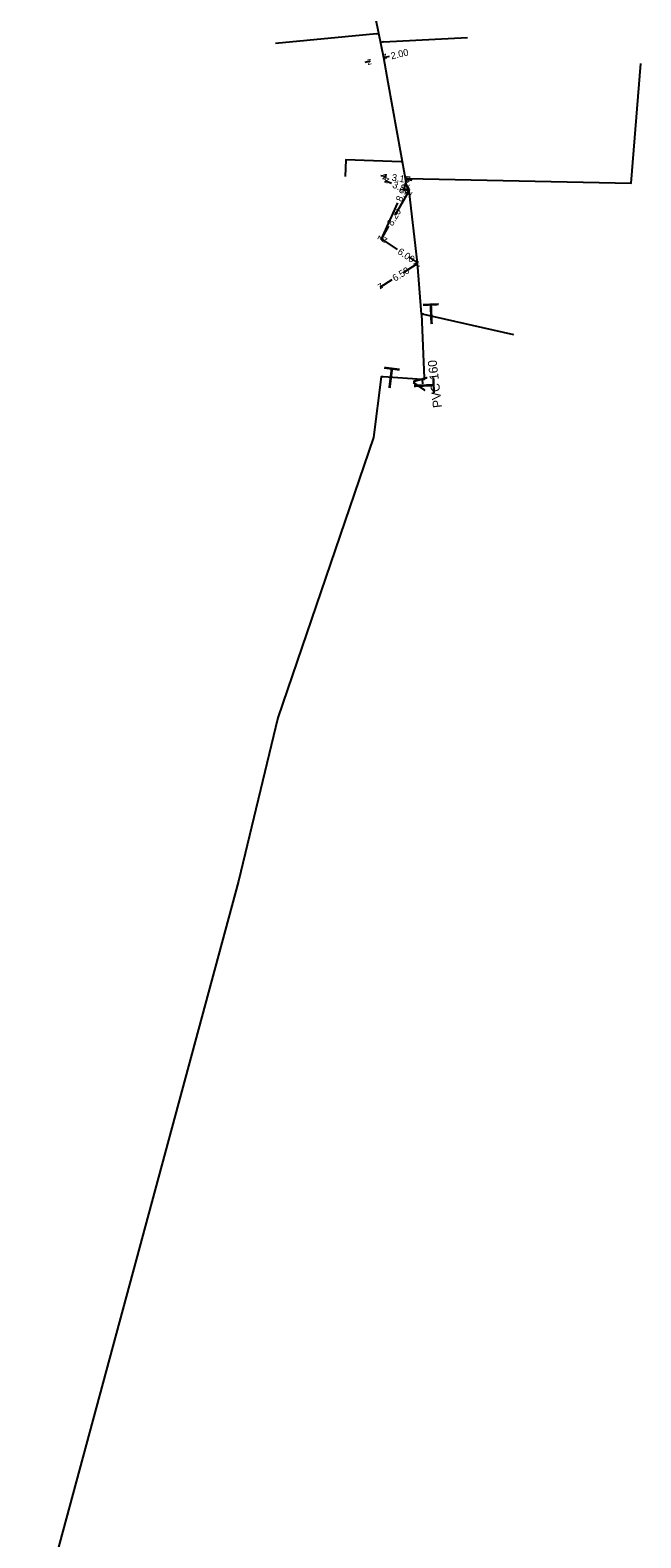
# Model space of a CAD drawing. Extents: x -634006 to -632185, y -1101085 to -1098649.
# Drawn here: x -633391.3 to -633302.8, y -1099867.2 to -1099648.6 of the extents above; entities that cross this region are included whole.
import ezdxf

# ---------------------------------------------------------------- set-up
doc = ezdxf.new("R2010")
doc.units = 0
for name, color, linetype in [('VP Hydrant', 7, 'Continuous'), ('VP Kótování', 7, 'Continuous'), ('VP Přípojka', 7, 'Continuous'), ('VP Řad', 7, 'Continuous'), ('VP Řad - popis', 7, 'Continuous'), ('VP Šoupě', 7, 'Continuous')]:
    doc.layers.add(name, color=color, linetype=linetype)

msp = doc.modelspace()

# ---------------------------------------------------------------- linework, layer by layer
at = {"layer": 'VP Kótování'}
for points in [[(-633342.75, -1099653.19), (-633342.02, -1099653.02)], [(-633339.3, -1099652.38), (-633340.08, -1099652.56)], [(-633340.51, -1099669.63), (-633339.77, -1099669.75)], [(-633338.96, -1099670.78), (-633339.87, -1099670.39)], [(-633339.82, -1099670.09), (-633339.72, -1099669.45)], [(-633339.62, -1099670.39), (-633339.62, -1099670.39)], [(-633337.19, -1099671.72), (-633336.81, -1099670.87)], [(-633337.15, -1099671.55), (-633336.38, -1099671.88)], [(-633337.11, -1099670.87), (-633337.11, -1099670.87)], [(-633336.76, -1099670.58), (-633336.66, -1099669.93)], [(-633335.97, -1099670.35), (-633336.71, -1099670.23)], [(-633338.06, -1099673.61), (-633340.51, -1099678.97)], [(-633338.38, -1099675.31), (-633336.38, -1099671.88)], [(-633336.62, -1099671.88), (-633336.63, -1099671.88)], [(-633336.59, -1099671.76), (-633336.59, -1099671.76)], [(-633339.37, -1099677.01), (-633340.51, -1099678.97)], [(-633340.72, -1099678.84), (-633340.72, -1099678.84)], [(-633340.3, -1099679.2), (-633340.3, -1099679.2)], [(-633340.21, -1099678.97), (-633340.21, -1099678.97)], [(-633338.1, -1099680.36), (-633340.16, -1099678.99)], [(-633337.23, -1099683.71), (-633335.16, -1099682.4)], [(-633336.41, -1099681.49), (-633335.16, -1099682.32)], [(-633334.92, -1099682.4), (-633334.92, -1099682.4)], [(-633335.3, -1099682.53), (-633335.3, -1099682.53)], [(-633338.92, -1099684.77), (-633340.66, -1099685.87)], [(-633340.41, -1099685.87), (-633340.41, -1099685.87)]]:
    msp.add_lwpolyline(points, dxfattribs=at)
at = {"layer": 'VP Přípojka'}
for points in [[(-633341.13, -1099649.11), (-633355.76, -1099650.52)], [(-633341.13, -1099649.11), (-633340.78, -1099649.04)], [(-633340.13, -1099650.26), (-633327.91, -1099649.64)], [(-633340.13, -1099650.26), (-633340.52, -1099650.34)], [(-633336.69, -1099670.06), (-633304.19, -1099670.74), (-633302.8, -1099653.42)], [(-633337.53, -1099667.65), (-633345.57, -1099667.37), (-633345.69, -1099669.79)], [(-633337.53, -1099667.65), (-633337.39, -1099667.62)], [(-633336.69, -1099670.06), (-633336.94, -1099670.09)], [(-633334.33, -1099689.74), (-633334.58, -1099689.75)], [(-633334.33, -1099689.74), (-633321.25, -1099692.67)], [(-633334.49, -1099699.2), (-633334.47, -1099699.86)]]:
    msp.add_lwpolyline(points, dxfattribs=at)
at = {"layer": 'VP Řad'}
for points in [[(-633334.58, -1099689.74), (-633335.16, -1099682.32), (-633336.38, -1099671.88), (-633336.81, -1099670.87), (-633336.94, -1099670.09), (-633339.43, -1099656.17), (-633340.08, -1099652.56), (-633340.82, -1099648.82), (-633344.28, -1099632.01)], [(-633334.58, -1099689.74), (-633334.23, -1099698.96), (-633334.22, -1099699.22), (-633334.49, -1099699.2), (-633340.18, -1099698.83), (-633340.43, -1099698.82), (-633341.54, -1099707.61), (-633355.45, -1099748.28), (-633361.15, -1099771.98), (-633389, -1099875.13), (-633391.35, -1099914.67), (-633358.54, -1100018.91), (-633322.36, -1100115.57), (-633326.19, -1100117.61)]]:
    msp.add_lwpolyline(points, dxfattribs=at)

# ---------------------------------------------------------------- texts
at = {"layer": 'VP Hydrant'}
msp.add_text('>', height=3, rotation=170.5409, dxfattribs=at).set_placement((-633333.48, -1099698.5))
at = {"layer": 'VP Kótování'}
for s, rotation, p in [('2.00', 13.326, (-633338.94, -1099652.81)), ('z', 13.326, (-633342.39, -1099653.62)), ('z', 193.326, (-633339.71, -1099651.96)), ('z', 351.0572, (-633340.34, -1099670.17)), ('z', 156.8622, (-633339.21, -1099670.13)), ('3.10', 351.0571, (-633338.97, -1099670.38)), ('3.80', 336.8622, (-633338.92, -1099671.34)), ('8.90', 65.4362, (-633337.48, -1099673.54)), ('z', 65.4362, (-633336.56, -1099671.53)), ('z', 336.8621, (-633337.03, -1099672.15)), ('z', 171.0572, (-633336.13, -1099669.81)), ('z', 59.7448, (-633336.2, -1099672.57)), ('8.20', 59.7448, (-633338.81, -1099677.05)), ('z', 245.4362, (-633340.75, -1099678.3)), ('z', 239.7448, (-633340.69, -1099678.28)), ('z', 146.3504, (-633339.46, -1099678.85)), ('6.00', 326.3505, (-633338.17, -1099680.91)), ('z', 326.3504, (-633335.86, -1099682.46)), ('z', 32.3011, (-633335.32, -1099683.09)), ('6.50', 32.3011, (-633338.44, -1099685.06)), ('z', 212.3011, (-633340.5, -1099685.18))]:
    msp.add_text(s, height=1, rotation=rotation, dxfattribs=at).set_placement(p)
at = {"layer": 'VP Řad - popis'}
msp.add_text('PVC 160', height=1.3, rotation=96.5547, dxfattribs=at).set_placement((-633331.63, -1099703.25))
at = {"layer": 'VP Šoupě'}
for rotation, p in [(2.3302, (-633334.36, -1099691.24)), (352.8365, (-633340.46, -1099700.31)), (272.3302, (-633335.73, -1099698.93))]:
    msp.add_text('T', height=3, rotation=rotation, dxfattribs=at).set_placement(p)

doc.saveas('drawing.dxf')
